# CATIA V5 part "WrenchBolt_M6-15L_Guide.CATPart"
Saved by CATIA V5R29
Part number: WrenchBolt_M6-15L_Guide
Bounding box of the stored display mesh (mm): x -5.11 to 5.11, y -5.11 to 5.11, z -15 to 6
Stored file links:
  C:\Users\Administrator\Desktop\프로젝트\Boxfold\Guide\WrenchBolt_M6-15L_Guide.CATPart
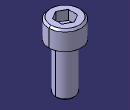
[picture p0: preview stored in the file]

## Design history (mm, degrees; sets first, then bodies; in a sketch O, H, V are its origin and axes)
Body1 (main body)
  Sketch1 on xy-plane, origin (0, 0, 0), H (1, 0, 0), V (0, 1, 0)
    circle A1 centre (0, 0) radius 5.11
    radius A1 = 5.11
  Pad1: profile Sketch1, direction (0, 0, 1), length 6
  Sketch2 on start face of Pad1, origin (0, 0, 0), H (1, 0, 0), V (0, -1, 0)
    circle A1 centre (0, 0) radius 3
    radius A1 = 3
  Pad2: profile Sketch2, direction (0, 0, -1), length 15
  Sketch3 on end face of Pad1, origin (0, 0, 6), H (1, 0, 0), V (0, 1, 0)
    point P1 (2.5475, 0)
    construction circle A1 centre (0, 0) radius 2.9416
    construction circle A2 centre (0, 0) radius 2.5475
    point P2 (2.5475, -1.4708)
    point P3 (2.5475, 1.4708)
    point P4 (0, 2.9416)
    point P5 (-2.5475, 1.4708)
    point P6 (-2.5475, -1.4708)
    point P7 (0, -2.9416)
    line L1 (2.5475, -1.4708) -> (2.5475, 1.4708)
    line L2 (2.5475, 1.4708) -> (0, 2.9416)
    line L3 (0, 2.9416) -> (-2.5475, 1.4708)
    line L4 (-2.5475, 1.4708) -> (-2.5475, -1.4708)
    line L5 (-2.5475, -1.4708) -> (0, -2.9416)
    line L6 (0, -2.9416) -> (2.5475, -1.4708)
    construction line L7 (0, 0) -> (2.5475, 0)
    radius A2 = 2.5475
    coincidence: A1 P2, A1 P3, A1 P4, A1 P5, A1 P6, A1 P7
    tangency: A2 L1, A2 L2, A2 L3, A2 L4, A2 L5, A2 L6
    midpoint: P1 L1
    horizontal: L7 H
  Pocket1: profile Sketch3, direction (0, 0, -1), length 3
  Thread1: "M6", diameter 6, depth 15, pitch 1, on face of Pad2 from Sketch2.A1, from end face of Pad2
  Chamfer1: length 0.6, angle 45, on end face of Pad2; edge [face of Pad1 from Sketch1.A1 | end face of Pad1]
  Fillet1: radius 0.25, on edge [start face of Pad1 | face of Pad2 from Sketch2.A1]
